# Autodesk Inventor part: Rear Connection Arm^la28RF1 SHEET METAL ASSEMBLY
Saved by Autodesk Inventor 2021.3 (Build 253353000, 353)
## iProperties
Created: 2023-01
Part Number: Rear Connection Arm^la28RF1 SHEET METAL ASSEMBLY
Material: Generic
Document SubType Name: Modeling
Designer: AdminForWorker
Density: 1 g/cm^3
Appearance: Default
Title: Rear Connection Arm^la28RF1 SHEET METAL ASSEMBLY
Author: AdminForWorker
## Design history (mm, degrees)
feature "Boss-Extrude1"
body "Solid1"
